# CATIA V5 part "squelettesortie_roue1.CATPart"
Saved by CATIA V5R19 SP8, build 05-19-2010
Part number: squelettesortie_roue1
Bounding box of the stored display mesh (mm): x 0 to 0, y -69.445 to 69.445, z -69.251 to 69.251
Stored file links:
  U:\Rendu_cfao_elguidj\squelettesortie_roue1.CATPart
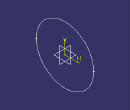
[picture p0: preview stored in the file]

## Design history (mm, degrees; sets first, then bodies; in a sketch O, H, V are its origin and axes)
Body1 (main body)
  Plane1: stored without definition
  Sketch1 on Plane1, origin (0, 0, 0), H (0, 1, 0), V (0, 0, 1)
    circle A1 centre (0, 0) radius 69.445
    radius A1 = 69.445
